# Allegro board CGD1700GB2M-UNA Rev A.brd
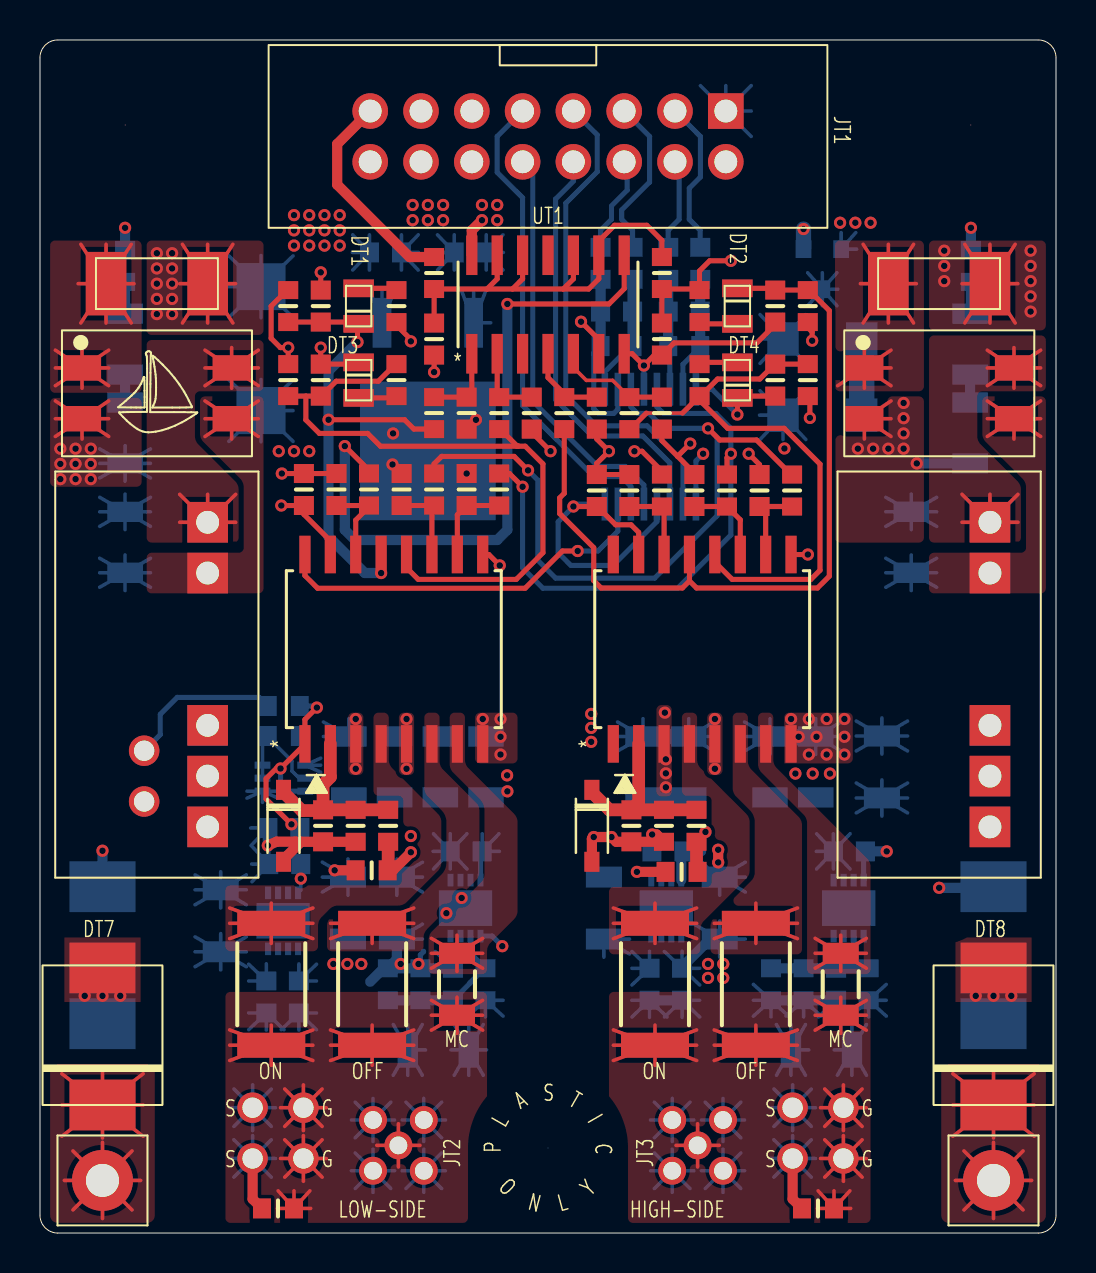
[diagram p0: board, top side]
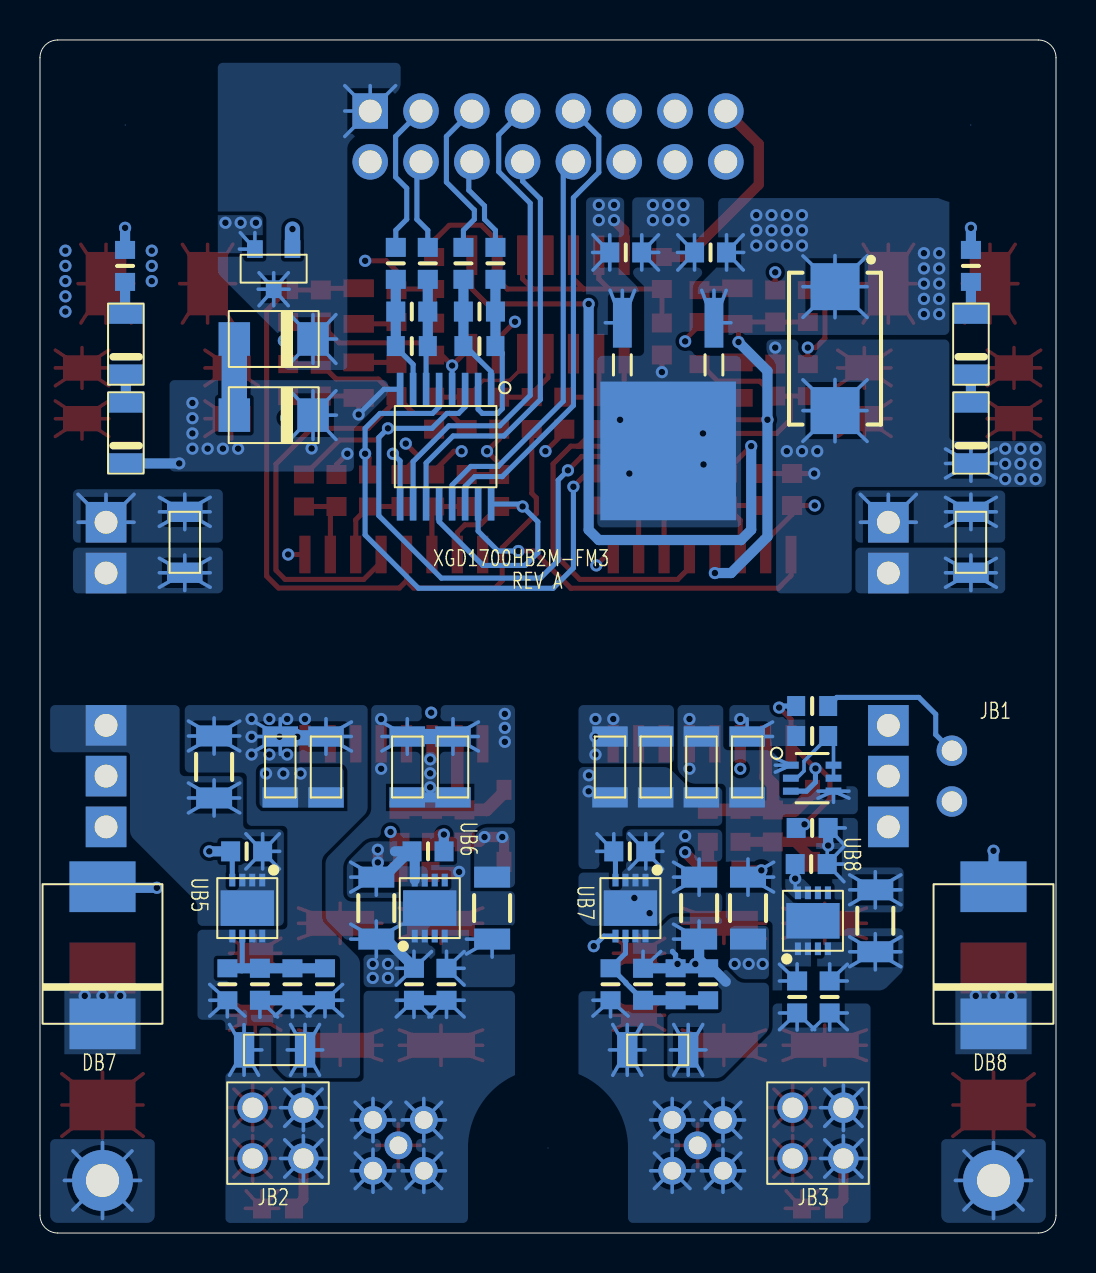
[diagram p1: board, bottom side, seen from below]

Outline 50.8 x 59.69 mm; copper layers: TOP, LAYER2, LAYER3, BOTTOM. Coordinates in mm from the lower left corner of the outline.
Outline path: 0,58.8 0,0.89 arc(0.26,0.26) 0.89,0 49.91,0 arc(50.54,0.26) 50.8,0.89 50.8,58.8 arc(50.54,59.43) 49.91,59.69 0.89,59.69 arc(0.26,59.43) 0,58.8

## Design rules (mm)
constraint set DEFAULT: min track width 0.178
net group FAULT-OUTPUT: nets FAULT-OUTPUT-N FAULT-OUTPUT-P
net group HS-PWM: nets HS-PWM-N HS-PWM-P
net group LS-PWM: nets LS-PWM-N LS-PWM-P
net group RTD-OUTPUT: nets RTD-OUTPUT-N RTD-OUTPUT-P
net group HIGH-SIDE: nets HS-OC N5948959 N6075364
net group LOW-SIDE: nets LS-OC N5949233 N6009832 N6072371 N6084683 RTD-ISO
net group PRIMARY: nets FAULT FLT_HS FLT_LS HS-PWM-INVERTED LS-PWM-INVERTED N5110410 N5786131 N5786223 N5786329 N5786365 N5791884 N5791888 N5813663 N5871306 N5927082 N5941912 N5941952 N6007380 N6007384 N6026363 N6026535 N6032095 N6073188 N6076004 N6088850 N6089152 N6093607 N6093609 PRE-BUFF-RESET RDY_HS RDY_LS RESET RESET INPUT RTD-NON-ISO

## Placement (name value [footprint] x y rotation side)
CB1  2.2uF  [CAPC1608X90N]  21.51 49.06 0 bottom
CB2  2.2uF  [CAPC1608X90N]  17.27 49.06 180 bottom
CB3  56 pF  [CAPC1608X90N]  32.21 46.1 0 bottom
CB4  56 pF  [CAPC1608X90N]  28.83 46.1 0 bottom
CB5  100uF  [CAPMP7343X430N]  11.05 44.25 270 bottom
CB6  10uF  [C_1206]  43.56 34.56 270 bottom
CB7  10uF  [C_1206]  4.25 34.56 270 bottom
CB8  10uF  [C_1206]  38.79 23.32 90 bottom
CB9  10uF  [C_1206]  36.5 23.32 90 bottom
CB10  10uF  [C_1206]  32.44 23.32 270 bottom
CB11  10uF  [C_1206]  30.15 23.32 270 bottom
CB12  10uF  [C_1206]  22.3 23.32 90 bottom
CB13  10uF  [C_1206]  20.02 23.32 90 bottom
CB14  10uF  [C_1206]  17.73 23.32 270 bottom
CB15  10uF  [C_1206]  15.44 23.32 90 bottom
CB16  10000pF  [CAPC1608X90N]  12.19 20.27 180 bottom
CB17  2.2uF  [CAPC1608X90N]  40.47 19.09 180 bottom
CB18  2.2uF  [CAPC1608X90N]  31.4 19.09 0 bottom
CB19  2.2uF  [CAPC1608X90N]  21.31 19.09 180 bottom
CB20  2.2uF  [CAPC1608X90N]  12.24 18.46 0 bottom
CB21  10000pF  [CAPC1608X90N]  39.81 12.45 90 bottom
CB22  2.2uF  [CAPC1608X90N]  32.1 12.45 90 bottom
CB23  10000pF  [CAPC1608X90N]  30.48 12.45 270 bottom
CB24  10000pF  [CAPC1608X90N]  20.65 12.45 270 bottom
CB25  2.2uF  [CAPC1608X90N]  12.94 11.81 90 bottom
CB26  10000pF  [CAPC1608X90N]  11.32 11.81 270 bottom
CB27  10uF  [C_1206]  39.07 9.16 0 bottom
CB28  10uF  [C_1206]  19.91 9.16 0 bottom
CT1  56 pF  [CAPC1608X90N]  14.04 46.38 90 top
CT2  56 pF  [CAPC1608X90N]  36.76 46.38 270 top
CT3  56 pF  [CAPC1608X90N]  19.71 44.73 270 top
CT4  2.2uF  [CAPC1608X90N]  31.09 44.73 270 top
CT5  56 pF  [CAPC1608X90N]  14.04 42.67 90 top
CT6  56 pF  [CAPC1608X90N]  36.76 42.67 270 top
CT7  56 pF  [CAPC1608X90N]  21.33 41.02 270 top
CT8  56 pF  [CAPC1608X90N]  24.59 41.02 270 top
CT9  56 pF  [CAPC1608X90N]  27.84 41.02 270 top
CT10  56 pF  [CAPC1608X90N]  31.09 41.02 270 top
CT11  2.2uF  [CAPC1608X90N]  13.2 37.2 90 top
CT12  56 pF  [CAPC1608X90N]  14.82 37.2 90 top
CT13  56 pF  [CAPC1608X90N]  18.08 37.2 90 top
CT14  56 pF  [CAPC1608X90N]  21.33 37.2 90 top
CT15  2.2uF  [CAPC1608X90N]  27.84 37.15 90 top
CT16  56 pF  [CAPC1608X90N]  29.47 37.15 90 top
CT17  56 pF  [CAPC1608X90N]  32.72 37.15 90 top
CT18  56 pF  [CAPC1608X90N]  35.98 37.15 90 top
CT19  56 pF  [CAPC1608X90N]  14.15 20.37 270 top
CT20  56 pF  [CAPC1608X90N]  29.57 20.37 270 top
DB1  SMAJ5932B-TP  [DO-214AC]  39.12 44.73 180 bottom
DB2  Purple  [D_1206]  46.51 44.47 270 bottom
DB3  Purple  [D_1206]  4.25 44.47 270 bottom
DB4  STPS2150A  [DO-214AC]  39.12 40.92 180 bottom
DB5  Purple  [D_1206]  46.51 40.03 270 bottom
DB6  Purple  [D_1206]  4.25 40.03 270 bottom
DB7  US3M-13  [DO-214AB-SMC]  47.68 10.47 90 bottom
DB8  US3M-13  [DO-214AB-SMC]  3.12 10.47 90 bottom
DT1  LH R974-LP-1  [D_0805]  15.93 46.38 270 top
DT2  LH R974-LP-1  [D_0805]  34.87 46.38 90 top
DT3  LG R971-KN-1  [D_0805]  15.93 42.67 90 top
DT4  LG R971-KN-1  [D_0805]  34.87 42.67 270 top
DT5  BAT42W-TP  [SOD123]  12.18 20.37 270 top
DT6  BAT42W-TP  [SOD123]  27.59 20.37 270 top
DT7  US3M-13  [DO-214AB-SMC]  3.12 6.4 90 top
DT8  US3M-13  [DO-214AB-SMC]  47.68 6.4 90 top
FT1  750 mA  [FUSE_SMD_SSQ2410]  5.84 47.5 180 top
FT2  750 mA  [FUSE_SMD_SSQ2410]  44.96 47.5 180 top
JB1  22-28-1020  [CONN_HEADER_RA_2POS_LOCKING]  5.21 22.86 180 bottom
JB2  SSW-102-01-G-D  [CON_2X2_100MIL_TH]  37.63 6.27 270 bottom
JB3  SSW-102-01-G-D  [CON_2X2_100MIL_TH]  10.63 6.27 270 bottom
JT1  SBH11-PBPC-D08-ST-BK  [CON_2X8_SHROUDED_CORRECTED]  34.29 56.13 270 top
JT2  MMCX-J-P-H-ST-TH1  [MMCX_PLUG_TH]  17.92 4.39 0 top
JT3  MMCX-J-P-H-ST-TH1  [MMCX_PLUG_TH]  32.88 4.39 0 top
JT4  735187-2  [CON_1X1_63MIL]  3.12 2.63 90 top
JT5  735187-2  [CON_1X1_63MIL]  47.68 2.63 90 top
LB1  1 uH  [INDC1608X95N]  33.01 48.51 270 bottom
LB2  1 uH  [INDC1608X95N]  31.41 48.51 270 bottom
LB3  1 uH  [INDC1608X95N]  29.63 48.51 270 bottom
LB4  1 uH  [INDC1608X95N]  28.03 48.51 270 bottom
LT1  10uH  [SRF0905]  5.85 42.01 0 top
LT2  10uH  [SRF0905]  44.96 42.01 0 top
NOREF  -  []  3.68 39.88 0 top
NOREF#2  -  [unnamed#2]  46.55 55.44 0 top
NOREF#3  -  [unnamed#2]  25.4 4.25 0 top
NOREF#4  -  [unnamed#2]  4.25 55.44 0 top
NOREF#5  -  []  25.4 0 90 top
NOREF#6  -  []  0 29.84 0 top
RB1  330  [RESC1608X55N]  46.55 48.39 90 bottom
RB2  330  [RESC1608X55N]  4.25 48.39 90 bottom
RB3  120  [RESC1608X55N]  32.21 44.37 180 bottom
RB4  120  [RESC1608X55N]  28.83 44.37 180 bottom
RB5  2.2k  [RESC1608X55N]  12.19 26.37 180 bottom
RB6  10k  [RESC1608X55N]  12.19 24.87 180 bottom
RB7  0  [RESC3216X70N]  42.09 23.32 90 bottom
RB8  0  [RESC3216X70N]  33.98 16.26 270 bottom
RB9  1.8M  [RESC3216X70N]  28.19 16.26 90 bottom
RB10  0  [RESC3216X70N]  17.84 16.26 270 bottom
RB11  0  [RESC3216X70N]  15.4 16.26 90 bottom
RB12  1.8M  [RESC3216X70N]  9.04 15.62 90 bottom
RB13  2.2k  [RESC1608X55N]  41.43 12.45 90 bottom
RB14  10k  [RESC1608X55N]  38.18 12.45 90 bottom
RB15  10k  [RESC1608X55N]  36.55 12.45 90 bottom
RB16  2.2k  [RESC1608X55N]  22.27 12.45 90 bottom
RB17  10k  [RESC1608X55N]  19.02 12.45 270 bottom
RB18  10k  [RESC1608X55N]  17.39 12.45 270 bottom
RT1  120  [RESC1608X55N]  19.71 48.03 90 top
RT2  10k  [RESC1608X55N]  31.09 48.03 90 top
RT3  10k  [RESC1608X55N]  12.41 46.38 270 top
RT4  330  [RESC1608X55N]  17.82 46.38 270 top
RT5  330  [RESC1608X55N]  32.98 46.38 90 top
RT6  10k  [RESC1608X55N]  38.39 46.38 90 top
RT7  120  [RESC1608X55N]  12.41 42.67 90 top
RT8  330  [RESC1608X55N]  17.82 42.67 90 top
RT9  330  [RESC1608X55N]  32.98 42.67 270 top
RT10  120  [RESC1608X55N]  38.39 42.67 270 top
RT11  120  [RESC1608X55N]  19.71 41.02 90 top
RT12  120  [RESC1608X55N]  22.96 41.02 90 top
RT13  120  [RESC1608X55N]  26.21 41.02 90 top
RT14  120  [RESC1608X55N]  29.47 41.02 90 top
RT15  120  [RESC1608X55N]  16.45 37.2 270 top
RT16  120  [RESC1608X55N]  19.71 37.2 270 top
RT17  120  [RESC1608X55N]  22.96 37.2 270 top
RT18  120  [RESC1608X55N]  31.09 37.15 270 top
RT19  120  [RESC1608X55N]  34.35 37.15 270 top
RT20  120  [RESC1608X55N]  37.6 37.15 270 top
RT21  330  [RESC1608X55N]  15.78 20.37 90 top
RT22  2.2k  [RESC1608X55N]  17.41 20.37 270 top
RT23  330  [RESC1608X55N]  31.2 20.37 90 top
RT24  2.2k  [RESC1608X55N]  32.83 20.37 270 top
RT25  330  [RESC1608X55N]  16.58 18.15 180 top
RT26  330  [RESC1608X55N]  32.08 18.07 180 top
RT27  1  [RESC6432X70N]  11.56 12.45 270 top
RT28  1  [RESC6432X70N]  16.61 12.45 270 top
RT29  0  [RESC3216X70N]  20.85 12.45 270 top
RT30  1  [RESC6432X70N]  30.75 12.45 270 top
RT31  1  [RESC6432X70N]  35.79 12.45 270 top
RT32  0  [RESC3216X70N]  40.04 12.45 270 top
RT33  10k  [RESC1608X55N]  11.9 1.23 180 top
RT34  10k  [RESC1608X55N]  38.9 1.23 180 top
UB1  DMP3056L-7  [SOT_23_3]  41.5 46.36 180 bottom
UB2  MC7805BDTG  [DPAK-3]  19.39 39.13 0 bottom
UB3  2/2  [TSSOP_16]  30.52 39.34 270 bottom
UB4  BC857BS  [SOT363_NEX]  12.19 22.76 180 bottom
UB5  LT3015EDD#TRPBF  [8-WDFN_EXPOSED_PAD]  40.44 16.26 270 bottom
UB6  LT3082EDD#PBF  [8-WDFN_EXPOSED_PAD]  31.31 16.26 90 bottom
UB7  LT3015EDD#TRPBF  [8-WDFN_EXPOSED_PAD]  21.28 16.26 270 bottom
UB8  LT3082EDD#PBF  [8-WDFN_EXPOSED_PAD]  12.15 15.62 90 bottom
UT1  AND_4_2x  [D14]  25.4 46.46 90 top
UT2  UCC21710  [DW16_TEX]  17.69 29.21 90 top
UT3  UCC21710  [DW16_TEX]  33.11 29.21 90 top
UT4  R15P21503D  [MGJ2]  8.38 35.56 270 top
UT5  R15P21503D  [MGJ2]  47.5 35.56 270 top

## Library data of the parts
CB1-CB4 CB6-CB28 CT1-CT20 = CAP
CB5 = CAP_P
DB1 = DIODE_ZENER
DB2 DB3 DB5 DB6 = LED - Purple
DB4 = DIODE_SCHOTTKY_12
DB7 DB8 DT7 DT8 = DIODE_1
DT1-DT4 = LED
DT5 DT6 = DIODE_SCHOTTKY_11
FT1 FT2 = FUSE
JB1 = CON2
JB2 JB3 = CON_2x2_100mil
JT1 = CON16A_Corrected
JT2 JT3 = BNC_5P
JT4 JT5 = HDR_1X1_M
LB1-LB4 = INDUCTOR
LT1 LT2 = CM choke - LPD3015_2
RB1-RB18 RT1-RT34 = RES
UB1 = MOSFET_P_GSD
UB2 = MC7805BDTG: User Part Number: TMP-1562; Tolerance: TOL
UB3 = SN65C1167
UB4 = DUAL_PNP: User Part Number: TMP-1677; Tolerance: TOL
UB5 UB7 = LT3015
UB6 UB8 = LT3082_0
UT1 = AND4_2X: User Part Number: TMP-1541; Tolerance: TOL
UT2 UT3 = UCC21710QDWRQ1: User Part Number: TMP-1688; Tolerance: TOL
UT4 UT5 = MGJ2

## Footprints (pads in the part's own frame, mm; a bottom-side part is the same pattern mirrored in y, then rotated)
8-WDFN_EXPOSED_PAD
  rect 0.635x0.305 smd: 1(-1.4,0.75) 2(-1.4,0.25) 3(-1.4,-0.25) 4(-1.4,-0.75) 5(1.4,-0.75) 6(1.4,-0.25) 7(1.4,0.25) 8(1.4,0.75)
  rect 1.778x2.667 smd: 9(0,0)
C_1206
  rect 1.016x1.778 smd: 1(-1.524,0) 2(1.524,0)
CAPC1608X90N
  rect 0.95x1 smd: 1(-0.8,0) 2(0.8,0)
CAPMP7343X430N
  rect 2.35x2.45 smd: 1(-3.1,0) 2(3.1,0)
CON_1X1_63MIL
  round 3.048 hole 1.651: 1(0,0)
CON_2X2_100MIL_TH
  round 1.524 hole 1.016: 1(0,0) 2(0,-2.54) 3(2.54,0) 4(2.54,-2.54)
CON_2X8_SHROUDED_CORRECTED
  rect 1.778x1.778 hole 1.143: 1(0,0)
  round 1.778 hole 1.143: 2(2.54,0) 3(0,-2.54) 4(2.54,-2.54) 5(0,-5.08) 6(2.54,-5.08) 7(0,-7.62) 8(2.54,-7.62) 9(0,-10.16) 10(2.54,-10.16) 11(0,-12.7) 12(2.54,-12.7) 13(0,-15.24) 14(2.54,-15.24) 15(0,-17.78) 16(2.54,-17.78)
CONN_HEADER_RA_2POS_LOCKING
  round 1.524 hole 1.016: 1(0,1.27) 2(0,-1.27)
D14
  rect 1.981x0.559 smd: 1(-2.464,3.81) 2(-2.464,2.54) 3(-2.464,1.27) 4(-2.464,0) 5(-2.464,-1.27) 6(-2.464,-2.54) 7(-2.464,-3.81) 8(2.464,-3.81) 9(2.464,-2.54) 10(2.464,-1.27) 11(2.464,0) 12(2.464,1.27) 13(2.464,2.54) 14(2.464,3.81)
D_0805
  rect 0.889x1.524 smd: 1(-0.889,0) 2(0.889,0)
D_1206
  rect 1.016x1.778 smd: 1(-1.524,0) 2(1.524,0)
DO-214AB-SMC
  rect 2.54x3.302 smd: A(6.858,0) C(0,0)
DO-214AC
  rect 1.575x1.676 smd: 1(1.968,0) 2(-1.968,0)
DPAK-3
  rect 0.94x2.489 smd: 1(-2.29,-6.413) 3(2.29,-6.413)
  rect 6.782x6.934 smd: 2(0,0)
DW16_TEX
  rect 1.88x0.559 smd: 1(-4.737,4.445) 2(-4.737,3.175) 3(-4.737,1.905) 4(-4.737,0.635) 5(-4.737,-0.635) 6(-4.737,-1.905) 7(-4.737,-3.175) 8(-4.737,-4.445) 9(4.737,-4.445) 10(4.737,-3.175) 11(4.737,-1.905) 12(4.737,-0.635) 13(4.737,0.635) 14(4.737,1.905) 15(4.737,3.175) 16(4.737,4.445)
FUSE_SMD_SSQ2410
  rect 2.032x3.175 smd: 1(-2.54,0) 2(2.54,0)
INDC1608X95N
  rect 0.95x1 smd: 1(-0.8,0) 2(0.8,0)
MGJ2
  rect 2.032x2.032 hole 1.143: 1(0,0) 2(2.54,0) 5(10.16,0) 6(12.7,0) 7(15.24,0)
MMCX_PLUG_TH
  round 1.397 hole 0.889: 1(0,0) 2(-1.27,1.27) 3(1.27,1.27) 4(1.27,-1.27) 5(-1.27,-1.27)
RESC1608X55N
  rect 0.9x1 smd: 1(-0.8,0) 2(0.8,0)
RESC3216X70N
  rect 1.05x1.8 smd: 1(-1.55,0) 2(1.55,0)
RESC6432X70N
  rect 1.25x3.4 smd: 1(-3.05,0) 2(3.05,0)
SOD123
  rect 1x0.75 smd: A(1.8,0) C(-1.8,0)
SOT363_NEX
  rect 0.787x0.356 smd: 1(-1.067,0.65) 2(-1.067,0) 3(-1.067,-0.65) 4(1.067,-0.65) 5(1.067,0) 6(1.067,0.65)
SOT_23_3
  rect 0.787x0.889 smd: 1(3.327,2.87) 2(1.448,2.87) 3(2.388,0.864)
SRF0905
  rect 1.905x1.27 smd: 1(-3.747,1.27) 2(-3.747,-1.27) 3(3.734,-1.27) 4(3.734,1.27)
TSSOP_16
  rect 1.651x0.33 smd: 1(-2.87,2.276) 2(-2.87,1.626) 3(-2.87,0.975) 4(-2.87,0.325) 5(-2.87,-0.325) 6(-2.87,-0.975) 7(-2.87,-1.626) 8(-2.87,-2.276) 9(2.87,-2.276) 10(2.87,-1.626) 11(2.87,-0.975) 12(2.87,-0.325) 13(2.87,0.325) 14(2.87,0.975) 15(2.87,1.626) 16(2.87,2.276)
unnamed#2
  round 0.025 hole 4.445 unplated: (0,0)

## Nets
5V: CB1.2 CT4.1 CT11.1 CT15.1 RT2.1 RT3.1 RT4.2 RT5.2 RT6.1 RT7.2 RT10.2 UB2.3(OUT) UB3.12 UB3.16(VCC) UT1.14 UT2.15 UT3.15
12V: CB2.2 CB5.1 FT1.1 FT2.1 RB1.2 RB2.2 UB1.2(S) UB2.1
+20V_HS: CB18.2 RB8.1 UB6.7 UB6.8 UT5.7
+20V_LS: CB20.2 RB11.1 UB8.7 UB8.8 UT4.7
-5V_HS: CB17.2 RB7.1 UB5.1 UB5.2 UB5.3(SHDN) UB5.9 UT5.5
-5V_LS: CB19.2 RB10.1 UB7.1 UB7.2 UB7.3(SHDN) UB7.9 UT4.5
0: CB1.1 CB2.1 CB5.2 CT1.2 CT2.2 CT3.2 CT4.2 CT5.2 CT6.2 CT7.2 CT8.2 CT9.2 CT10.2 CT11.2 CT12.2 CT13.2 CT14.2 CT15.2 CT16.2 CT17.2 CT18.2 DB4.1(C) DB5.2(CATHODE) DB6.2(CATHODE) DT3.2(C) DT4.2(C) JT1.2 JT1.12 JT1.14 JT1.16 LT1.2 LT2.2 UB1.1 UB2.2 UB3.4 UB3.8 UT1.7 UT2.9 UT3.9
FAULT: UB3.9 UT1.6
FAULT-OUTPUT-N: JT1.8 UB3.11
FAULT-OUTPUT-P: JT1.7 UB3.10
FLT_HS: CT2.1 DT2.2(C) RT6.2 RT13.1 UT3.13
FLT_LS: CT1.1 DT1.2(C) RT3.2 RT11.1 UT2.13
HS-DM: DB7.C(CATHODE) DT8.A
HS-DRAIN: DT8.C(CATHODE) JT5.1
HS-GATE: JB2.2 JB2.4 JT3.1(SIGNAL) RT30.2 RT31.2 RT32.2 RT34.1
HS-OC: CT20.1 DT6.C RT23.2 RT24.1 UT3.2
HS-PWM-INVERTED: RT17.1 RT19.1 UB3.5
HS-PWM-N: JT1.4 LB2.1
HS-PWM-P: JT1.3 LB1.1
HS-SOURCE: CB8.1 CB9.1 CB10.2 CB11.2 CB17.1 CB18.1 CB22.1 CB23.2 CB27.2 CT20.2 DT6.A JB2.1 JB2.3 JT3.2 JT3.3 JT3.4 JT3.5 RB9.2 RB13.1 RT23.1 RT34.2 UB5.4 UB5.5 UT3.3 UT5.6(COM)
HS-VDD: CB10.1 CB11.1 CB22.2 RB8.2 RT26.2 UB6.1 UB6.2 UB6.9 UT3.5
HS-VSS: CB8.2 CB9.2 CB21.1 CB27.1 RB7.2 RB14.1 RB15.1 UB5.7 UB5.8 UT3.8(VEE)
LS-DM: DB8.C(CATHODE) DT7.A
LS-DRAIN: DT7.C(CATHODE) JT4.1
LS-GATE: JB3.2 JB3.4 JT2.1(SIGNAL) RT27.2 RT28.2 RT29.2 RT33.1
LS-OC: CT19.1 DT5.C RT21.2 RT22.1 UT2.2
LS-PWM-INVERTED: RT16.1 RT20.1 UB3.3
LS-PWM-N: JT1.6 LB4.1
LS-PWM-P: JT1.5 LB3.1
LS-SOURCE: CB12.1 CB13.1 CB14.2 CB15.2 CB16.2 CB19.1 CB20.1 CB25.1 CB26.2 CB28.2 CT19.2 DT5.A JB1.2 JB3.1 JB3.3 JT2.2 JT2.3 JT2.4 JT2.5 RB6.1 RB12.2 RB16.1 RT21.1 RT33.2 UB7.4 UB7.5 UT2.3 UT4.6(COM)
LS-VDD: CB14.1 CB15.1 CB25.2 RB11.2 RT25.2 UB4.1 UB4.4(EMITTER) UB8.1 UB8.2 UB8.9 UT2.5
LS-VSS: CB12.2 CB13.2 CB24.1 CB28.1 RB10.2 RB17.1 RB18.1 UB7.7 UB7.8 UT2.8(VEE)
MILLERCLAMP-HS: RT32.1 UT3.7
MILLERCLAMP-LS: RT29.1 UT2.7
NC2: UT1.3
PRE-BUFF-RESET: CT3.1 RT1.1 RT2.2 UT1.9 UT1.10 UT1.12 UT1.13
RDY_HS: CT6.1 RT9.2 RT10.1 RT14.1 UT3.12
RDY_LS: CT5.1 RT7.1 RT8.2 RT12.1 UT2.12
RESET: RT15.1 RT18.1 UT1.8(Y)
RESET INPUT: JT1.15 RT1.2
RTD-ISO: CB16.1 RB5.1 UB4.3 UT2.1
RTD-NON-ISO: UB3.15 UT2.16
RTD-OUTPUT-N: JT1.10 UB3.13
RTD-OUTPUT-P: JT1.9 UB3.14
UNPROTECTED_VIN: DB1.1(C) JT1.1 UB1.3
VOUT_OFF_HS: RT31.1 UT3.6
VOUT_OFF_LS: RT28.1 UT2.6
VOUT_ON_HS: RT30.1 UT3.4
VOUT_ON_LS: RT27.1 UT2.4
N5110410: CT14.1 RT17.2 UT2.10
N5777665: CB6.1 LT2.4 UT5.1
N5777737: CB6.2 LT2.3 UT5.2
N5778706: CB7.1 LT1.4 UT4.1
N5778794: CB7.2 LT1.3 UT4.2
N5780153: FT1.2 LT1.1
N5786131: CB4.1 LB4.2 RB4.2 UB3.2
N5786223: CB4.2 LB3.2 RB4.1 UB3.1
N5786329: CB3.1 LB2.2 RB3.2 UB3.6
N5786365: CB3.2 LB1.2 RB3.1 UB3.7
N5791884: DT1.1 RT4.1
N5791888: DT2.1 RT5.1
N5813663: CT7.1 RT11.2 UT1.1
N5871306: CT9.1 RT13.2 UT1.4
N5927082: DB1.2 DB4.2
N5941912: CT8.1 RT12.2 UT1.2
N5941952: CT10.1 RT14.2 UT1.5
N5948959: CB21.2 RB13.2 RB14.2 RB15.2 UB5.6
N5949233: CB24.2 RB16.2 RB17.2 RB18.2 UB7.6
N6007380: DT3.1 RT8.1
N6007384: DT4.1 RT9.1
N6009832: DB8.A RT22.2 RT25.1
N6026363: CT18.1 RT20.2 UT3.10
N6026535: CT16.1 RT18.2 UT3.14
N6032095: CT12.1 RT15.2 UT2.14
N6067568: CB23.1 RB9.1 UB6.4(SET)
N6067584: CB26.1 RB12.1 UB8.4(SET)
N6072371: JB1.1 RB5.2
N6073188: CT13.1 RT16.2 UT2.11
N6075364: DB7.A RT24.2 RT26.1
N6076004: CT17.1 RT19.2 UT3.11
N6084683: RB6.2 UB4.2 UB4.5 UB4.6
N6088850: DB2.2(CATHODE) DB5.1
N6089152: DB3.2(CATHODE) DB6.1
N6093449: FT2.2 LT2.1
N6093607: DB3.1 RB2.1
N6093609: DB2.1 RB1.1

Pads without a net: JT1 11 13; UB6 3 5 6; UB8 3 5 6; UT1 11; UT3 1 16

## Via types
v1: diameter 0.61, hole 0.33, TOP to BOTTOM, 171 vias

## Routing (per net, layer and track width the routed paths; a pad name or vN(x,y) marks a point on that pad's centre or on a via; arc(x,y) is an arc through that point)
5V: length 47.7
  TOP w0.254: UT3.15 29.93,35.05 29.55,35.43 28.78,35.43 27.87,36.35 CT15.1 v1(26.67,36.35) ; v1(18.54,44.61) 18.54,44.7 17.82,45.42 RT4.2 ; v1(38.61,44.64) 38.61,45.09 38.39,45.3 RT6.1 ; RT3.1 12.36,47.18 11.56,46.37 11.56,44.76 12.02,44.3 v1(12.41,44.3) RT7.2 ; UT2.15 14.52,34.63 13.2,35.95 CT11.1 v1(12.06,36.4) ; v1(38.49,40.78) 38.49,41.77 RT10.2 ; v1(34.54,48.64) 33.48,48.64 32.98,48.14 RT5.2 32.92,47.23 RT2.1 CT4.1
  TOP w0.508: v1(22.1,50.67) 21.59,50.16 UT1.14
  BOTTOM w0.178: UB2.3 21.68,47.17 ; UB2.3 21.07,47.17 ; UB2.3 22.53,45.54 ; UB2.3 22.3,47.17 ; CB1.2 23.15,48.18 ; CB1.2 23.15,49.94 ; CB1.2 23.17,49.06 ; CB1.2 22.31,49.94 ; CB1.2 22.31,48.18
  BOTTOM w0.254: UB3.16 26.79,36.47 v1(26.67,36.35) 25.91,35.59 25.91,34.04 26.54,33.4 28.65,33.4 30.84,35.59 UB3.12
  vias: v1(22.1,51.44) v1(22.86,51.44) v1(22.86,50.67)
12V: length 63.3
  TOP w0.178: FT2.1 47.5,49.47 ; FT2.1 48.76,49.47 ; FT2.1 48.9,47.5 ; FT2.1 46.1,47.5 ; FT2.1 47.5,45.53 ; FT2.1 46.24,45.53 ; FT2.1 46.24,49.47 ; FT2.1 48.76,45.53 ; 6.98,47.5 FT1.1 ; FT1.1 9.78,47.5 ; FT1.1 7.12,45.53 ; FT1.1 8.38,45.53 ; FT1.1 9.64,45.53 ; FT1.1 8.38,49.47 ; FT1.1 9.64,49.47 ; FT1.1 7.12,49.47
  BOTTOM w0.178: CB5.1 12.66,47.35 ; CB5.1 11.05,45.79 ; CB5.1 12.66,45.81 ; CB5.1 11.05,48.9 ; CB5.1 12.66,48.89 ; CB5.1 9.44,45.81 ; CB5.1 9.44,47.35 ; CB5.1 9.44,48.89 ; 15.62,49.06 CB2.2 ; CB2.2 16.47,48.18 ; CB2.2 15.63,49.94 ; CB2.2 15.63,48.18 ; CB2.2 16.47,49.94 ; UB2.1 17.72,47.17 ; UB2.1 16.25,45.54 ; UB2.1 17.1,47.17 ; UB2.1 16.49,47.17 ; UB1.2 40.83,49.23 ; UB1.2 40.06,50.05 ; UB1.2 40.79,50.05
  BOTTOM w0.508: RB2.2 v1(4.25,50.29) ; RB1.2 v1(46.55,50.29)
  vias: v1(5.84,49.02) v1(5.84,48.26) v1(5.84,47.5) v1(5.84,46.74) v1(5.84,45.97) v1(6.6,49.02) v1(6.6,48.26) v1(6.6,47.5) v1(6.6,46.74) v1(6.6,45.97) v1(12.7,50.93) v1(12.7,50.16) v1(12.7,49.4) v1(13.46,50.93) v1(13.46,50.16) v1(13.46,49.4) v1(14.22,50.93) v1(14.22,50.16) v1(14.22,49.4) v1(14.99,50.93) v1(14.99,50.16) v1(14.99,49.4) v1(40,50.55) v1(40.77,50.55) v1(41.53,50.55) v1(45.21,49.15) v1(45.21,48.39) v1(45.21,47.62) v1(49.53,49.15) v1(49.53,48.39) v1(49.53,47.62) v1(49.53,46.86) v1(49.53,46.1)
+20V_HS: length 24.1
  TOP w0.508: v1(33.91,19.18) v1(33.91,18.54)
  LAYER3 w0.178: UT5.7 48.9,21.72 ; UT5.7 48.9,18.92 ; UT5.7 47.5,18.92 ; UT5.7 48.9,20.32 ; UT5.7 46.1,20.32 ; UT5.7 46.1,21.72 ; UT5.7 46.1,18.92
  BOTTOM w0.178: RB8.1 35.27,18.55 ; RB8.1 35.27,17.81 ; RB8.1 33.98,16.9 ; RB8.1 33.98,18.71 ; RB8.1 35.27,17.06
  BOTTOM w0.508: v1(33.91,18.54) 33.91,17.88 RB8.1 33.61,17.81 32.32,19.09 ; 32.32,19.09 CB18.2 32.06,18.96 UB6.8 ; 32.32,19.09 33.06,19.09
+20V_LS: length 9.6
  LAYER3 w0.178: UT4.7 9.78,18.92 ; UT4.7 8.38,18.92 ; UT4.7 6.98,18.92 ; UT4.7 6.98,20.32 ; UT4.7 9.78,20.32
  BOTTOM w0.178: CB20.2 v1(13.04,17.73) 13.04,17.16 UB8.8
  vias: v1(14.67,13.46) v1(15.37,13.46) v1(16.07,13.46)
-5V_HS: length 17.8
  BOTTOM w0.178: 38.83,18.21 CB17.2 ; CB17.2 38.81,19.09 ; CB17.2 40.51,19.98 ; CB17.2 38.83,19.98 ; CB17.2 39.67,18.21 ; CB17.2 40.51,18.21 ; CB17.2 39.67,19.98 ; RB7.1 43.38,21.77 ; RB7.1 43.38,21.02 ; RB7.1 40.81,21.02 ; RB7.1 40.81,22.52 ; RB7.1 42.09,20.86 ; RB7.1 43.38,22.52 ; RB7.1 40.81,21.77 ; RB7.1 42.09,22.67
-5V_LS: length 13.5
  BOTTOM w0.178: 19.65,19.09 CB19.2 ; CB19.2 21.35,19.98 ; CB19.2 20.51,19.98 ; CB19.2 21.35,18.21 ; CB19.2 20.51,18.21 ; CB19.2 19.67,18.21 ; CB19.2 19.67,19.98 ; RB10.1 19.13,17.81 ; RB10.1 17.84,16.9 ; RB10.1 19.13,18.55 ; RB10.1 19.13,17.06 ; RB10.1 17.84,18.71
  vias: v1(18.54,19.86) v1(20.32,16) v1(21.08,16.76)
0: length 140.4
  TOP w0.178: LT1.2 3.44,40.74 ; LT1.2 3.44,39.85 ; LT1.2 0.77,39.85 ; LT1.2 2.1,39.73 ; LT1.2 0.77,41.63 ; LT1.2 3.44,41.63 ; LT1.2 0.77,40.74 ; LT2.2 42.55,41.63 ; LT2.2 42.55,40.74 ; LT2.2 41.22,39.73 ; LT2.2 42.55,39.85
  TOP w0.254: CT18.2 35.98,38.45 v1(35.43,38.99) ; v1(12.09,38) CT11.2 CT12.2 ; CT13.2 v1(17.62,38.45) ; CT16.2 CT15.2 27.84,38.51 v1(28.45,39.12) 27.84,39.72 CT9.2 ; v1(25.53,39.12) 24.59,40.06 CT8.2 ; 31.88,38.86 32.72,38.02 CT17.2 ; 31.88,38.86 31.09,39.64 CT10.2 ; 31.88,38.86 31.88,38.86 v1(32.51,39.5) ; UT3.9 v1(38.39,33.95) ; v1(34.87,40.95) DT4.2 34.96,41.87 CT6.2 ; CT1.2 v1(14.04,48.07) ; DT3.2 15.84,43.47 CT5.2 v1(14.04,44.3) ; CT3.2 v1(19.71,43.07) ; UT2.9 22.44,33.95 v1(22.99,33.4) ; UT1.7 29.6,43.99 v1(30.19,43.4) 30.72,43.93 CT4.2 31.7,44.54 35.84,44.54 36.76,45.46 CT2.2 ; CT7.2 v1(21.8,40.69)
  LAYER2 w0.178: 15.48,54.62 16.51,53.59 ; 16.51,53.59 16.51,54.86 ; 16.51,53.59 16.51,52.32 ; 16.51,53.59 17.54,54.62 ; 16.51,53.59 17.54,52.57 ; 16.51,53.59 15.48,52.57 ; 16.51,53.59 15.24,53.59 ; 34.29,53.59 35.32,52.57 ; 34.29,53.59 33.26,54.62 ; 34.29,53.59 35.32,54.62 ; 34.29,53.59 33.26,52.57 ; 34.29,53.59 35.56,53.59 ; 34.29,53.59 33.02,53.59 ; 34.29,53.59 34.29,54.86 ; 34.29,53.59 34.29,52.32 ; 21.59,53.59 22.62,52.57 ; 21.59,53.59 21.59,54.86 ; 21.59,53.59 20.56,54.62 ; 21.59,53.59 22.62,54.62 ; 21.59,53.59 22.86,53.59 ; 21.59,53.59 20.56,52.57 ; 21.59,53.59 21.59,52.32 ; 19.05,53.59 20.08,54.62 ; 19.05,53.59 18.02,54.62 ; 19.05,53.59 19.05,54.86 ; 19.05,53.59 20.08,52.57 ; 19.05,53.59 19.05,52.32 ; 19.05,53.59 18.02,52.57
  BOTTOM w0.178: 37.15,39.7 DB4.1 ; DB4.1 37.15,42.14 ; DB4.1 36,39.7 ; DB4.1 38.29,39.7 ; DB4.1 36,42.14 ; DB4.1 38.29,42.14 ; DB4.1 35.98,40.92 ; 2.98,39.23 DB6.2 ; DB6.2 5.52,38.5 ; DB6.2 2.98,37.78 ; DB6.2 4.25,39.39 ; DB6.2 5.52,39.23 ; DB6.2 2.98,38.5 ; DB6.2 5.52,37.78 ; DB6.2 4.25,37.61 ; 19.86,49.06 CB1.1 ; CB1.1 19.88,48.18 ; CB1.1 19.88,49.94 ; CB1.1 20.71,49.94 ; CB1.1 20.71,48.18 ; CB5.2 12.66,42.69 ; CB5.2 11.05,42.7 ; CB5.2 9.44,41.15 ; CB5.2 12.66,39.61 ; CB5.2 9.44,39.61 ; CB5.2 9.44,42.69 ; CB5.2 12.66,41.15 ; CB5.2 11.05,39.59 ; CB2.1 18.91,49.94 ; CB2.1 18.93,49.06 ; CB2.1 18.07,48.18 ; CB2.1 18.91,48.18 ; CB2.1 18.07,49.94
  BOTTOM w0.254: v1(34.87,40.95) 33.61,42.21 UB3.8 ; UB3.4 v1(30.19,43.4)
  BOTTOM w0.508: DB5.2 v1(43.84,38.5)
  BOTTOM w0.762: UB1.1 v1(38.18,50.23)
  vias: v1(1.02,39.24) v1(1.02,38.48) v1(1.02,37.72) v1(1.78,39.24) v1(1.78,38.48) v1(1.78,37.72) v1(2.54,39.24) v1(2.54,38.48) v1(2.54,37.72) v1(11.94,39.12) v1(12.7,39.12) v1(13.46,39.12) v1(17.65,40) v1(18.63,51.44) v1(18.63,50.67) v1(19.39,51.44) v1(19.39,50.67) v1(20.15,51.44) v1(20.15,50.67) v1(21.33,38) v1(37.22,39.25) v1(40.89,39.24) v1(41.66,39.24) v1(42.42,39.24) v1(43.18,41.53) v1(43.18,40.77) v1(43.18,40) v1(43.18,39.24)
FAULT: length 14.4
  TOP w0.254: v1(27.05,45.59) 27.94,44.7 UT1.6
  LAYER3 w0.254: v1(33.16,38.99) 33.05,38.89 32.26,38.89 27.05,44.1 v1(27.05,45.59)
  BOTTOM w0.254: UB3.9 32.8,38.63 v1(33.16,38.99)
FAULT-OUTPUT-N: length 21.3
  BOTTOM w0.254: UB3.11 31.49,38.53 30.14,39.88 27.6,39.88 25.78,41.7 25.78,51.73 26.67,52.62 26.67,53.59
FAULT-OUTPUT-P: length 24.7
  BOTTOM w0.254: UB3.10 32.15,38.6 30.35,40.39 27.81,40.39 26.29,41.91 26.29,51.52 27.86,53.1 27.86,54.94 JT1.7
FLT_HS: length 40.5
  TOP w0.254: 32.47,32.63 32.83,32.27 38.87,32.27 39.47,32.86 39.47,46.15 38.44,47.18 RT6.2 CT2.1 36.67,47.27 DT2.2 ; 32.47,32.63 32.12,32.27 28.05,32.27 27.69,32.64 27.69,34.29 25.98,35.99 25.98,36.78 26.21,37.01 RT13.1 ; 32.47,32.63 UT3.13
FLT_LS: length 24.6
  TOP w0.254: v1(15.87,44.58) 15.87,45.43 DT1.2 15.84,45.58 CT1.1 RT3.2 ; UT2.13 v1(17.06,33.02) ; RT11.1 18.7,40.22 18.23,40.69 v1(14.43,40.69)
  BOTTOM w0.508: v1(15.87,44.58) 14.43,43.13 v1(14.43,40.69) 14.43,34.84 16.24,33.02 v1(17.06,33.02)
HS-DM:
  vias: v1(46.79,11.87) v1(47.68,11.87) v1(48.56,11.87)
HS-DRAIN: length 81.5
  TOP w0.178: 47.68,4.75 DT8.C ; DT8.C 49.71,6.4 ; DT8.C 45.64,6.4 ; DT8.C 45.64,7.97 ; DT8.C 49.71,4.84 ; DT8.C 49.71,7.97 ; DT8.C 45.64,4.84 ; DT8.C 47.68,8.06 ; JT5.1 47.68,4.54 ; JT5.1 49.58,2.63 ; JT5.1 49.15,4.11 ; JT5.1 46.2,4.11 ; JT5.1 46.2,1.16 ; JT5.1 47.68,0.73 ; JT5.1 49.15,1.16 ; JT5.1 45.77,2.63
  LAYER2 w0.178: 46.2,4.11 JT5.1 ; JT5.1 45.77,2.63 ; JT5.1 47.68,4.54 ; JT5.1 47.68,0.73 ; JT5.1 49.15,1.16 ; JT5.1 46.2,1.16 ; JT5.1 49.58,2.63 ; JT5.1 49.15,4.11
  LAYER3 w0.178: 46.2,1.16 JT5.1 ; JT5.1 45.77,2.63 ; JT5.1 47.68,4.54 ; JT5.1 49.58,2.63 ; JT5.1 49.15,1.16 ; JT5.1 47.68,0.73 ; JT5.1 49.15,4.11 ; JT5.1 46.2,4.11
  BOTTOM w0.178: JT5.1 47.68,4.54 ; JT5.1 49.58,2.63 ; JT5.1 49.15,4.11 ; JT5.1 49.15,1.16 ; JT5.1 47.68,0.73 ; JT5.1 46.2,4.11 ; JT5.1 46.2,1.16 ; JT5.1 45.77,2.63
HS-GATE: length 69.4
  TOP w0.178: 33.71,9.4 RT31.2 ; RT31.2 33.71,10.16 ; RT31.2 37.87,8.63 ; RT31.2 33.71,8.63 ; RT31.2 35.79,10.4 ; RT31.2 35.79,8.39 ; RT31.2 37.87,9.4 ; RT31.2 37.87,10.16 ; JT3.1 33.96,4.39 ; JT3.1 32.88,5.47 ; JT3.1 31.8,4.39 ; JT3.1 32.88,3.31 ; JB2.2 40.17,7.41 ; JB2.2 39.23,7.21 ; JB2.2 41.31,6.27 ; JB2.2 39.23,5.33 ; JB2.2 40.17,5.13 ; JB2.2 41.11,7.21 ; JB2.2 39.03,6.27 ; JB2.2 41.11,5.33 ; RT30.2 32.83,9.4 ; RT30.2 28.67,8.63 ; RT30.2 28.67,10.16 ; RT30.2 32.83,10.16 ; RT30.2 32.83,8.63 ; RT30.2 28.67,9.4 ; RT30.2 30.75,10.4 ; RT30.2 30.75,8.39 ; RT34.1 39.7,2.11 ; RT34.1 40.49,2.11 ; RT34.1 38.87,1.23 ; RT34.1 38.91,2.11 ; RT34.1 40.53,1.23 ; JB2.4 41.31,3.73 ; JB2.4 40.17,2.59 ; JB2.4 41.11,4.67 ; JB2.4 41.11,2.79 ; JB2.4 39.23,4.67 ; JB2.4 39.03,3.73 ; JB2.4 39.23,2.79 ; JB2.4 40.17,4.87 ; RT32.2 41.32,11.64 ; RT32.2 41.32,10.9 ; RT32.2 40.04,11.8 ; RT32.2 38.75,10.15 ; RT32.2 38.75,10.9 ; RT32.2 38.75,11.64 ; RT32.2 40.04,9.99 ; RT32.2 41.32,10.15
HS-OC: length 9.2
  TOP w0.635: CT20.1 28.47,21.17 27.59,22.05 DT6.C ; CT20.1 RT23.2 RT24.1 ; CT20.1 29.93,21.54 UT3.2
HS-PWM-INVERTED: length 28.9
  TOP w0.254: RT19.1 34.35,38.79 v1(34.54,38.99) ; v1(24.13,37.34) 23.47,38 RT17.1
  BOTTOM w0.254: v1(24.13,37.34) 24.13,33.27 25.15,32.26 31.88,32.26 34.54,34.92 v1(34.54,38.99) 34.54,40.26 33.8,41.01 31.17,41.01 30.84,41.33 UB3.5
HS-PWM-N: length 4.6
  BOTTOM w0.254: 31.75,53.59 31.96,53.39 31.96,50.72 31.41,50.17 LB2.1
HS-PWM-P: length 7.8
  BOTTOM w0.254: LB1.1 33.01,50.17 32.46,50.72 32.46,52.28 33.02,52.83 33.02,54.86 JT1.3
HS-SOURCE: length 210.9
  TOP w0.508: v1(30.61,19.94) 30.83,19.94 RT23.1 CT20.2 28.81,19.57 v1(28.57,19.81) v1(27.69,19.81) 27.59,19.72 DT6.A ; JB2.3 37.63,1.7 RT34.2
  LAYER2 w0.178: 46.1,21.46 UT5.6 ; UT5.6 48.9,24.26 ; UT5.6 46.1,24.26 ; UT5.6 48.9,21.46 ; UT5.6 46.1,22.86 ; UT5.6 48.9,22.86 ; 30.72,2.22 JT3.5 ; JT3.5 30.72,4.01 ; JT3.5 32.69,3.12 ; JT3.5 30.53,3.12 ; JT3.5 31.61,4.2 ; JT3.5 32.5,2.22 ; JT3.5 31.61,2.04 ; JT3.3 35.04,4.76 ; JT3.3 35.04,6.55 ; JT3.3 33.26,6.55 ; JT3.3 34.15,4.58 ; JT3.3 33.07,5.66 ; JT3.3 35.23,5.66 ; JT3.3 34.15,6.74 ; JT3.4 35.23,3.12 ; JT3.4 33.07,3.12 ; JT3.4 35.04,4.01 ; JT3.4 33.26,2.22 ; JT3.4 35.04,2.22 ; JT3.4 34.15,2.04 ; JT3.4 34.15,4.2 ; JT3.2 31.61,6.74 ; JT3.2 32.5,6.55 ; JT3.2 30.72,4.76 ; JT3.2 30.53,5.66 ; JT3.2 32.69,5.66 ; JT3.2 30.72,6.55 ; JT3.2 31.61,4.58 ; 37.63,5.13 JB2.1 ; JB2.1 38.57,7.21 ; JB2.1 37.63,7.41 ; JB2.1 36.69,7.21 ; JB2.1 36.49,6.27 ; JB2.1 38.77,6.27 ; JB2.1 36.69,5.33 ; JB2.1 38.57,5.33 ; 36.69,4.67 JB2.3 ; JB2.3 38.57,2.79 ; JB2.3 37.63,2.59 ; JB2.3 38.77,3.73 ; JB2.3 36.49,3.73 ; JB2.3 36.69,2.79 ; JB2.3 37.63,4.87 ; JB2.3 38.57,4.67
  LAYER3 w0.178: JB2.1 38.57,5.33 ; JB2.1 37.63,7.41 ; JB2.1 36.69,7.21 ; JB2.1 38.77,6.27 ; JB2.1 38.57,7.21 ; JB2.1 37.63,5.13 ; JB2.1 36.49,6.27 ; JB2.1 36.69,5.33 ; 30.72,4.76 JT3.2 ; JT3.2 30.72,6.55 ; JT3.2 32.69,5.66 ; JT3.2 31.61,4.58 ; JT3.2 31.61,6.74 ; JT3.2 30.53,5.66 ; JT3.2 32.5,6.55 ; 36.49,3.73 JB2.3 ; JB2.3 38.57,4.67 ; JB2.3 37.63,4.87 ; JB2.3 38.77,3.73 ; JB2.3 36.69,4.67 ; JB2.3 37.63,2.59 ; JB2.3 38.57,2.79 ; JB2.3 36.69,2.79 ; JT3.3 34.15,6.74 ; JT3.3 34.15,4.58 ; JT3.3 35.04,6.55 ; JT3.3 33.26,6.55 ; JT3.3 33.07,5.66 ; JT3.3 35.04,4.76 ; JT3.3 35.23,5.66 ; JT3.5 31.61,4.2 ; JT3.5 32.5,2.22 ; JT3.5 30.72,2.22 ; JT3.5 30.72,4.01 ; JT3.5 31.61,2.04 ; JT3.5 32.69,3.12 ; JT3.5 30.53,3.12 ; UT5.6 48.9,24.26 ; UT5.6 46.1,24.26 ; UT5.6 46.1,22.86 ; UT5.6 48.9,22.86 ; 33.26,2.22 JT3.4 ; JT3.4 35.04,2.22 ; JT3.4 34.15,4.2 ; JT3.4 34.15,2.04 ; JT3.4 35.04,4.01 ; JT3.4 35.23,3.12 ; JT3.4 33.07,3.12
  BOTTOM w0.178: 34.15,2.04 JT3.4 ; JT3.4 35.23,3.12 ; JT3.4 33.07,3.12 ; JT3.4 35.04,4.01 ; JT3.4 33.26,2.22 ; JT3.4 35.04,2.22 ; JT3.4 34.15,4.2 ; RB13.1 42.31,12.44 ; RB13.1 42.31,10.85 ; RB13.1 40.55,10.85 ; RB13.1 42.31,11.65 ; RB13.1 41.43,10.81 ; 33.07,5.66 JT3.3 ; JT3.3 35.23,5.66 ; JT3.3 34.15,4.58 ; JT3.3 33.26,6.55 ; JT3.3 35.04,4.76 ; JT3.3 35.04,6.55 ; JT3.3 34.15,6.74 ; CB23.2 31.36,10.81 ; CB23.2 29.59,11.65 ; CB23.2 29.59,10.81 ; CB23.2 30.48,10.79 ; 36.69,4.67 JB2.3 ; JB2.3 38.77,3.73 ; JB2.3 38.57,2.79 ; JB2.3 36.69,2.79 ; JB2.3 37.63,2.59 ; JB2.3 38.57,4.67 ; JB2.3 36.49,3.73 ; JB2.3 37.63,4.87 ; 31.22,10.81 CB22.1 ; CB22.1 32.1,10.79 ; CB22.1 32.98,10.81 ; CB22.1 32.98,11.65 ; 37.63,5.13 JB2.1 ; JB2.1 38.77,6.27 ; JB2.1 38.57,5.33 ; JB2.1 36.69,5.33 ; JB2.1 38.57,7.21 ; JB2.1 37.63,7.41 ; JB2.1 36.49,6.27 ; JB2.1 36.69,7.21 ; JT3.5 32.69,3.12 ; JT3.5 32.5,2.22 ; JT3.5 31.61,4.2 ; JT3.5 30.72,2.22 ; JT3.5 30.72,4.01 ; JT3.5 30.53,3.12 ; JT3.5 31.61,2.04 ; JT3.2 32.69,5.66 ; JT3.2 31.61,6.74 ; JT3.2 30.72,4.76 ; JT3.2 30.72,6.55 ; JT3.2 30.53,5.66 ; JT3.2 32.5,6.55 ; JT3.2 31.61,4.58 ; 39.87,7.89 CB27.2 ; CB27.2 41.32,10.43 ; CB27.2 41.32,7.89 ; CB27.2 40.6,10.43 ; CB27.2 40.6,7.89 ; CB27.2 39.71,9.16
  BOTTOM w0.254: UB5.4 41.19,19.01 CB17.1
  BOTTOM w0.508: v1(30.61,19.94) 30.61,19.1 CB18.1 ; CB22.1 CB23.2 ; CB17.1 v1(42.34,19.09) ; CB10.2 CB11.2
  vias: v1(31.24,26.04) v1(31.29,23.7) v1(31.29,23) v1(31.29,22.3) v1(37.77,22.99) v1(38.63,22.99) v1(39.5,22.99)
HS-VDD: length 28.4
  TOP w0.508: RT26.2 v1(29.84,18.07)
  BOTTOM w0.178: RB8.2 33.98,15.61 ; RB8.2 33.98,13.8 ; RB8.2 35.27,15.45 ; RB8.2 35.27,14.71 ; RB8.2 32.7,15.45 ; CB22.2 32.98,13.25 ; CB22.2 31.22,14.08 ; CB22.2 32.98,12.41 ; CB10.1 33.71,24.84 ; CB10.1 33.71,25.57 ; CB10.1 33.71,24.12 ; CB10.1 32.44,25.73 ; CB10.1 32.44,23.95 ; 28.88,24.12 CB11.1 ; CB11.1 30.15,23.95 ; CB11.1 28.88,24.84 ; CB11.1 28.88,25.57 ; CB11.1 30.15,25.73 ; 32.1,13.31 32.1,14.1
  BOTTOM w0.508: RB8.2 33.5,14.71 32.1,13.31 CB22.2
  BOTTOM w0.762: CB10.1 CB11.1
  vias: v1(27.56,25.97) v1(27.56,25.27) v1(27.56,24.57) v1(33.4,13.46) v1(33.4,12.76) v1(33.74,25.72) v1(33.74,23.23) v1(34.16,13.46) v1(34.16,12.76)
HS-VSS: length 48.6
  BOTTOM w0.178: 38.18,10.81 RB14.1 ; RB14.1 37.3,10.85 ; RB14.1 39.06,10.85 ; 40.81,24.87 RB7.2 ; RB7.2 43.38,25.61 ; RB7.2 42.09,23.96 ; RB7.2 40.81,24.12 ; RB7.2 43.38,24.87 ; RB7.2 43.38,24.12 ; RB7.2 40.81,25.61 ; RB7.2 42.09,25.77 ; CB27.1 38.27,7.89 ; CB27.1 37.55,7.89 ; CB27.1 36.82,10.43 ; CB27.1 38.44,9.16 ; CB27.1 36.82,7.89 ; CB27.1 37.55,10.43 ; CB27.1 36.66,9.16 ; CB27.1 38.27,10.43 ; 35.23,25.57 CB9.2 ; CB9.2 36.5,25.73 ; CB9.2 35.23,24.12 ; CB9.2 36.5,23.95 ; CB9.2 35.23,24.84 ; 36.55,10.81 RB15.1 ; RB15.1 35.67,10.85 ; RB15.1 35.67,11.65 ; RB15.1 37.43,10.85 ; RB15.1 35.67,12.44 ; 38.92,10.81 CB21.1 39.81,10.79 ; CB8.2 40.06,24.12 ; CB8.2 40.06,25.57 ; CB8.2 40.06,24.84 ; CB8.2 38.79,23.95 ; CB8.2 38.79,25.73
  BOTTOM w0.508: CB21.1 RB14.1 RB15.1
  BOTTOM w0.762: CB8.2 38.01,24.84 37.94,24.78 37.16,24.78 37.1,24.84 CB9.2
  vias: v1(37.55,25.72) v1(37.93,24.83) v1(38.44,25.72) v1(38.44,23.94) v1(38.82,24.83) v1(39.33,25.72) v1(39.33,23.94) v1(40.22,25.72) v1(40.22,24.83) v1(40.22,23.94)
LS-DM:
  vias: v1(2.24,11.87) v1(3.12,11.87) v1(4.01,11.87)
LS-DRAIN: length 81.5
  TOP w0.178: JT4.1 4.6,4.11 ; JT4.1 3.12,4.54 ; JT4.1 4.6,1.16 ; JT4.1 5.03,2.63 ; JT4.1 1.65,4.11 ; JT4.1 1.22,2.63 ; JT4.1 1.65,1.16 ; JT4.1 3.12,0.73 ; 1.09,4.84 DT7.C ; DT7.C 1.09,6.4 ; DT7.C 3.12,8.06 ; DT7.C 5.16,4.84 ; DT7.C 5.16,7.97 ; DT7.C 3.12,4.75 ; DT7.C 5.16,6.4 ; DT7.C 1.09,7.97
  LAYER2 w0.178: 1.65,4.11 JT4.1 ; JT4.1 5.03,2.63 ; JT4.1 3.12,0.73 ; JT4.1 4.6,1.16 ; JT4.1 4.6,4.11 ; JT4.1 1.65,1.16 ; JT4.1 1.22,2.63 ; JT4.1 3.12,4.54
  LAYER3 w0.178: 1.22,2.63 JT4.1 ; JT4.1 3.12,4.54 ; JT4.1 3.12,0.73 ; JT4.1 4.6,4.11 ; JT4.1 4.6,1.16 ; JT4.1 1.65,4.11 ; JT4.1 1.65,1.16 ; JT4.1 5.03,2.63
  BOTTOM w0.178: 1.22,2.63 JT4.1 ; JT4.1 1.65,4.11 ; JT4.1 1.65,1.16 ; JT4.1 3.12,4.54 ; JT4.1 4.6,1.16 ; JT4.1 3.12,0.73 ; JT4.1 5.03,2.63 ; JT4.1 4.6,4.11
LS-GATE: length 69.4
  TOP w0.178: 9.48,10.16 RT27.2 ; RT27.2 9.48,9.4 ; RT27.2 13.65,8.63 ; RT27.2 11.56,10.4 ; RT27.2 9.48,8.63 ; RT27.2 13.65,10.16 ; RT27.2 13.65,9.4 ; RT27.2 11.56,8.39 ; 19.57,10.15 RT29.2 ; RT29.2 22.13,10.9 ; RT29.2 22.13,10.15 ; RT29.2 19.57,10.9 ; RT29.2 22.13,11.64 ; RT29.2 19.57,11.64 ; RT29.2 20.85,11.8 ; RT29.2 20.85,9.99 ; JB3.2 14.11,5.33 ; JB3.2 12.23,5.33 ; JB3.2 14.31,6.27 ; JB3.2 13.17,7.41 ; JB3.2 13.17,5.13 ; JB3.2 12.03,6.27 ; JB3.2 14.11,7.21 ; JB3.2 12.23,7.21 ; 12.23,4.67 JB3.4 ; JB3.4 13.17,2.59 ; JB3.4 14.11,4.67 ; JB3.4 14.31,3.73 ; JB3.4 14.11,2.79 ; JB3.4 12.03,3.73 ; JB3.4 12.23,2.79 ; JB3.4 13.17,4.87 ; 16.84,4.39 JT2.1 ; JT2.1 19,4.39 ; JT2.1 17.92,5.47 ; JT2.1 17.92,3.31 ; RT28.2 18.69,8.63 ; RT28.2 16.61,10.4 ; RT28.2 14.53,9.4 ; RT28.2 18.69,10.16 ; RT28.2 14.53,10.16 ; RT28.2 18.69,9.4 ; RT28.2 16.61,8.39 ; RT28.2 14.53,8.63 ; 11.91,2.11 RT33.1 ; RT33.1 12.7,2.11 ; RT33.1 13.49,2.11 ; RT33.1 11.87,1.23 ; RT33.1 13.53,1.23
LS-OC: length 9.2
  TOP w0.635: CT19.1 RT21.2 RT22.1 ; CT19.1 14.11,21.13 13.09,21.13 12.18,22.05 DT5.C ; CT19.1 14.15,22.45 14.52,22.81 UT2.2
LS-PWM-INVERTED: length 35.9
  TOP w0.254: RT16.1 19.71,38.48 20.08,38.85 23.71,38.85 v1(24.4,38.16) ; RT20.1 37.55,37.95 35.83,39.67 33.99,39.67 v1(33.4,40.26)
  BOTTOM w0.254: UB3.3 29.54,41.33 29.87,41.01 30.45,41.01 31.2,40.26 v1(33.4,40.26) 33.86,39.8 33.86,35.89 30.73,32.77 25.78,32.77 24.89,33.66 24.89,37.67 v1(24.4,38.16)
LS-PWM-N: length 4.9
  BOTTOM w0.254: 29.21,53.59 29.36,53.45 29.36,52.18 28.57,51.39 28.57,50.72 28.03,50.17 LB4.1
LS-PWM-P: length 8.2
  BOTTOM w0.254: JT1.5 30.48,54.86 30.48,52.58 29.08,51.18 29.08,50.72 29.63,50.17 LB3.1
LS-SOURCE: length 246.2
  TOP w0.508: RT33.2 10.63,1.7 JB3.3 ; DT5.A 12.18,18.7 13.05,19.57 ; 13.05,19.57 12.77,19.57 12.76,19.58 11.83,19.58 v1(11.39,19.39) ; 13.05,19.57 CT19.2 RT21.1
  LAYER2 w0.178: JT2.3 20.08,6.55 ; JT2.3 20.08,4.76 ; JT2.3 19.19,6.74 ; JT2.3 18.11,5.66 ; JT2.3 18.3,6.55 ; JT2.3 20.27,5.66 ; JT2.3 19.19,4.58 ; JT2.4 20.27,3.12 ; JT2.4 19.19,4.2 ; JT2.4 18.11,3.12 ; JT2.4 20.08,4.01 ; JT2.4 20.08,2.22 ; JT2.4 19.19,2.04 ; JT2.4 18.3,2.22 ; 15.57,5.66 JT2.2 ; JT2.2 17.73,5.66 ; JT2.2 15.76,6.55 ; JT2.2 15.76,4.76 ; JT2.2 17.54,6.55 ; JT2.2 16.65,4.58 ; JT2.2 16.65,6.74 ; JT2.5 17.54,2.22 ; JT2.5 15.57,3.12 ; JT2.5 15.76,2.22 ; JT2.5 16.65,2.04 ; JT2.5 17.73,3.12 ; JT2.5 15.76,4.01 ; JT2.5 16.65,4.2 ; JB3.3 11.77,3.73 ; JB3.3 10.63,2.59 ; JB3.3 10.63,4.87 ; JB3.3 9.49,3.73 ; JB3.3 9.69,4.67 ; JB3.3 11.57,4.67 ; JB3.3 9.69,2.79 ; JB3.3 11.57,2.79 ; 4.27,20.65 JB1.2 ; JB1.2 4.06,21.59 ; JB1.2 5.21,20.45 ; JB1.2 6.14,22.53 ; JB1.2 6.35,21.59 ; JB1.2 5.21,22.73 ; JB1.2 6.14,20.65 ; JB1.2 4.27,22.53 ; 9.49,6.27 JB3.1 ; JB3.1 11.77,6.27 ; JB3.1 11.57,7.21 ; JB3.1 9.69,5.33 ; JB3.1 10.63,5.13 ; JB3.1 11.57,5.33 ; JB3.1 10.63,7.41 ; JB3.1 9.69,7.21 ; 6.98,21.46 UT4.6 ; UT4.6 6.98,24.26 ; UT4.6 9.78,21.46 ; UT4.6 9.78,24.26 ; UT4.6 9.78,22.86 ; UT4.6 6.98,22.86
  LAYER3 w0.178: JT2.2 17.54,6.55 ; JT2.2 15.57,5.66 ; JT2.2 16.65,4.58 ; JT2.2 17.73,5.66 ; JT2.2 15.76,6.55 ; JT2.2 15.76,4.76 ; JT2.2 16.65,6.74 ; 10.63,2.59 JB3.3 ; JB3.3 11.57,2.79 ; JB3.3 9.69,2.79 ; JB3.3 9.49,3.73 ; JB3.3 11.57,4.67 ; JB3.3 11.77,3.73 ; JB3.3 9.69,4.67 ; JB3.3 10.63,4.87 ; JB3.1 10.63,7.41 ; JB3.1 11.57,7.21 ; JB3.1 9.69,7.21 ; JB3.1 9.69,5.33 ; JB3.1 11.57,5.33 ; JB3.1 11.77,6.27 ; JB3.1 9.49,6.27 ; JB3.1 10.63,5.13 ; 18.11,3.12 JT2.4 ; JT2.4 20.08,4.01 ; JT2.4 18.3,2.22 ; JT2.4 19.19,2.04 ; JT2.4 19.19,4.2 ; JT2.4 20.27,3.12 ; JT2.4 20.08,2.22 ; 16.65,2.04 JT2.5 ; JT2.5 15.76,2.22 ; JT2.5 15.76,4.01 ; JT2.5 16.65,4.2 ; JT2.5 15.57,3.12 ; JT2.5 17.73,3.12 ; JT2.5 17.54,2.22 ; JB1.2 5.21,22.73 ; JB1.2 6.14,20.65 ; JB1.2 4.27,22.53 ; JB1.2 6.14,22.53 ; JB1.2 5.21,20.45 ; JB1.2 6.35,21.59 ; JB1.2 4.06,21.59 ; JB1.2 4.27,20.65 ; JT2.3 19.19,6.74 ; JT2.3 18.3,6.55 ; JT2.3 20.08,4.76 ; JT2.3 19.19,4.58 ; JT2.3 20.27,5.66 ; JT2.3 18.11,5.66 ; JT2.3 20.08,6.55
  LAYER3 w1.27: UT4.6 6.86,22.86
  BOTTOM w0.178: JB3.1 11.77,6.27 ; JB3.1 11.57,5.33 ; JB3.1 9.69,5.33 ; JB3.1 9.69,7.21 ; JB3.1 11.57,7.21 ; JB3.1 9.49,6.27 ; JB3.1 10.63,7.41 ; JB3.1 10.63,5.13 ; 19.19,2.04 JT2.4 ; JT2.4 18.3,2.22 ; JT2.4 20.08,2.22 ; JT2.4 20.27,3.12 ; JT2.4 20.08,4.01 ; JT2.4 19.19,4.2 ; JT2.4 18.11,3.12 ; JB3.3 11.57,4.67 ; JB3.3 10.63,2.59 ; JB3.3 9.49,3.73 ; JB3.3 11.57,2.79 ; JB3.3 10.63,4.87 ; JB3.3 11.77,3.73 ; JB3.3 9.69,2.79 ; JB3.3 9.69,4.67 ; RB16.1 23.16,10.85 ; RB16.1 21.39,10.85 ; RB16.1 22.27,10.81 ; RB16.1 23.16,11.65 ; 10.6,19.34 CB20.1 ; CB20.1 10.58,18.46 ; CB20.1 10.6,17.58 ; CB20.1 11.44,19.34 ; 7.75,17.17 RB12.2 ; RB12.2 7.75,16.42 ; RB12.2 7.75,17.92 ; RB12.2 10.32,16.42 ; RB12.2 10.32,17.92 ; RB12.2 10.32,17.17 ; RB12.2 9.04,18.08 ; RB12.2 9.04,16.26 ; 20.71,10.43 CB28.2 ; CB28.2 21.44,7.89 ; CB28.2 20.71,7.89 ; CB28.2 22.16,7.89 ; CB28.2 20.55,9.16 ; CB28.2 21.44,10.43 ; CB28.2 22.16,10.43 ; CB28.2 22.33,9.16 ; 19.19,4.58 JT2.3 ; JT2.3 18.11,5.66 ; JT2.3 19.19,6.74 ; JT2.3 20.08,4.76 ; JT2.3 20.08,6.55 ; JT2.3 18.3,6.55 ; JT2.3 20.27,5.66 ; CB19.1 22.11,19.98 ; CB19.1 22.95,19.98 ; CB19.1 22.97,19.09 ; 12.06,10.17 CB25.1 ; CB25.1 13.83,11.01 ; CB25.1 12.94,10.15 ; CB25.1 13.83,10.17 ; 14.17,25.57 CB15.2 ; CB15.2 15.44,25.73 ; CB15.2 14.17,24.84 ; JT2.2 17.73,5.66 ; JT2.2 15.76,6.55 ; JT2.2 15.57,5.66 ; JT2.2 15.76,4.76 ; JT2.2 16.65,6.74 ; JT2.2 16.65,4.58 ; JT2.2 17.54,6.55 ; JT2.5 17.73,3.12 ; JT2.5 16.65,2.04 ; JT2.5 17.54,2.22 ; JT2.5 15.76,2.22 ; JT2.5 15.76,4.01 ; JT2.5 15.57,3.12 ; JT2.5 16.65,4.2 ; 10.43,11.01 CB26.2 ; CB26.2 12.2,10.17 ; CB26.2 10.43,10.17 ; CB26.2 11.32,10.15 ; 10.55,19.39 CB16.2 10.54,20.27
  BOTTOM w0.254: CB19.1 22.03,19.01 UB7.4 ; v1(23.11,14.35) 22.61,14.86 UB7.5
  BOTTOM w0.508: CB16.2 v1(11.39,19.39)
  vias: v1(15.79,25.72) v1(15.79,23.23) v1(23.36,22.9) v1(23.37,22.1)
LS-VDD: length 16.4
  TOP w0.508: RT25.2 v1(14.73,18.15)
  BOTTOM w0.178: CB25.2 12.94,13.47 ; CB25.2 13.83,12.61 ; CB25.2 13.83,13.45 ; 14.12,17.06 RB11.2 ; RB11.2 15.4,18.71 ; RB11.2 14.12,18.55 ; RB11.2 14.12,17.81 ; RB11.2 15.4,16.9 ; UB4.4 11.9,21.76 ; UB4.4 10.35,22.11 ; UB4.4 11.9,22.11 ; UB4.4 10.35,21.76 ; UB4.4 11.13,21.55 ; UB4.1 14.03,23.06 ; UB4.1 14.03,23.76 ; UB4.1 14.03,23.41
  vias: v1(18.33,25.72) v1(18.33,23.23)
LS-VSS: length 22.9
  BOTTOM w0.178: 18.39,7.89 CB28.1 ; CB28.1 19.28,9.16 ; CB28.1 18.39,10.43 ; CB28.1 17.5,9.16 ; CB28.1 17.66,7.89 ; CB28.1 19.12,10.43 ; CB28.1 19.12,7.89 ; CB28.1 17.66,10.43 ; RB10.2 19.13,14.71 ; RB10.2 19.13,15.45 ; RB10.2 17.84,15.61 ; 19.76,14.08 CB24.1 20.65,14.1
  BOTTOM w0.254: RB17.1 19.02,13.92 19.18,14.08 19.18,14.1
  BOTTOM w0.508: RB10.2 17.84,13.7 RB18.1 ; 16.51,12.57 17.18,13.25 RB18.1 ; RB18.1 RB17.1 CB24.1
  vias: v1(18.03,13.46) v1(18.92,13.46) v1(22.14,25.72) v1(23.03,25.72) v1(23.03,24.83) v1(23.03,23.94)
MILLERCLAMP-HS: length 10.3
  TOP w0.178: RT32.1 41.32,14.74 ; RT32.1 38.75,14 ; RT32.1 41.32,13.25 ; RT32.1 41.32,14 ; RT32.1 38.75,14.74 ; RT32.1 40.04,13.09 ; RT32.1 40.04,14.9 ; RT32.1 38.75,13.25
MILLERCLAMP-LS: length 10.3
  TOP w0.178: RT29.1 22.13,13.25 ; RT29.1 19.57,14 ; RT29.1 20.85,13.09 ; RT29.1 22.13,14 ; RT29.1 19.57,14.74 ; RT29.1 20.85,14.9 ; RT29.1 22.13,14.74 ; RT29.1 19.57,13.25
PRE-BUFF-RESET: length 22.4
  TOP w0.254: UT1.10 26.67,47.74 26.16,47.23 ; 22.35,47.23 RT1.1 CT3.1 ; 22.35,47.23 22.86,47.74 UT1.13 ; 22.35,47.23 23.62,47.23 ; 26.16,47.23 23.62,47.23 ; 26.16,47.23 27.43,47.23 27.94,47.74 UT1.9 27.94,49.63 28.73,50.42 30.34,50.42 31.09,49.66 RT2.2 ; 23.62,47.23 24.13,47.74 UT1.12
RDY_HS: length 29.3
  TOP w0.178: 30.32,41.02 32.12,41.02
  TOP w0.254: UT3.12 33.74,33.57 34.61,32.7 38.54,32.7 39,33.16 39,38.47 37.21,40.26 34.39,40.26 33.03,41.62 33.03,41.87 ; 33.03,41.87 33.88,42.73 35.99,42.73 36.74,43.47 CT6.1 RT10.1 ; 33.03,41.87 RT9.2 32.12,41.02 ; RT14.1 29.52,40.22 30.32,41.02
RDY_LS: length 34
  TOP w0.254: 23.86,39.37 23.92,39.37 23.93,39.37 24.26,39.37 25.15,38.48 25.15,34.04 23.81,32.7 18.91,32.7 18.33,33.29 UT2.12 ; 23.86,39.37 23.01,40.22 RT12.1 ; 23.86,39.37 23.85,39.36 17.02,39.36 16.38,40 13.97,40 13.29,40.68 13.29,41.87 ; 13.29,41.87 RT7.1 ; 13.29,41.87 CT5.1 14.06,41.87 14.81,42.62 16.92,42.62 17.77,43.47 RT8.2
RESET: length 45.7
  TOP w0.254: RT15.1 16.45,38.16 v1(15.24,39.37) ; v1(23.37,46.48) 28.45,46.48 29.21,47.24 UT1.8 ; RT18.1 31.09,38.12 30.1,39.11 v1(29.72,39.11)
  LAYER3 w0.254: v1(29.72,39.11) 23.37,45.47 v1(23.37,46.48)
  BOTTOM w0.508: v1(23.37,46.48) 23.37,35.18 22.86,34.67 15.75,34.67 15.24,35.18 v1(15.24,39.37)
RESET INPUT: length 10.7
  TOP w0.508: JT1.15 14.86,54.48 14.86,52.45 18.48,48.83 RT1.2
RTD-ISO: length 11
  TOP w0.254: v1(13.84,26.29) 13.25,25.69 UT2.1 13.25,24.46 v1(12.03,23.24) 11.81,23.24 11.3,22.73 11.3,21.72 v1(12.57,20.45)
  BOTTOM w0.254: v1(12.03,23.24) 12.03,22.56 12.48,22.11 UB4.3 ; CB16.1 12.75,20.27 v1(12.57,20.45) ; v1(13.84,26.29) 13.77,26.37 RB5.1
RTD-NON-ISO: length 19.5
  TOP w0.254: v1(26.88,34.12) 26.12,34.12 24.26,32.26 13.88,32.26 13.25,32.89 UT2.16
  BOTTOM w0.254: v1(26.88,34.12) 27.9,34.12 28.89,35.12 UB3.15
RTD-OUTPUT-N: length 20.4
  BOTTOM w0.254: 24.13,53.59 24.64,53.09 24.64,41.61 27.9,38.35 29.26,38.35 30.19,37.42 UB3.13
RTD-OUTPUT-P: length 23.8
  BOTTOM w0.254: JT1.9 22.86,54.86 22.86,53.07 24.13,51.8 24.13,41.4 27.69,37.85 29.05,37.85 29.54,37.35 UB3.14
UNPROTECTED_VIN: length 25.9
  BOTTOM w0.178: UB1.3 39.85,48.05 ; UB1.3 39.89,47.22 ; UB1.3 38.38,46.39 ; UB1.3 39.12,48.05 ; UB1.3 39.85,46.39 ; UB1.3 38.34,47.22 ; UB1.3 38.38,48.05 ; UB1.3 39.12,46.39 ; DB1.1 38.29,45.95 ; DB1.1 36,45.95 ; DB1.1 37.15,43.51 ; DB1.1 36,43.51 ; DB1.1 37.15,45.95 ; DB1.1 35.98,44.73 ; DB1.1 38.29,43.51 ; JT1.1 34.29,57.4 ; JT1.1 35.56,57.4 ; JT1.1 33.02,57.4 ; JT1.1 35.56,56.13 ; JT1.1 35.56,54.86
VOUT_OFF_HS: length 12.8
  TOP w0.178: 35.79,14.49 RT31.1 ; RT31.1 37.87,16.26 ; RT31.1 33.71,15.5 ; RT31.1 37.87,14.73 ; RT31.1 33.71,14.73 ; RT31.1 35.79,16.5 ; RT31.1 37.87,15.5
VOUT_OFF_LS: length 11.8
  TOP w0.178: RT28.1 18.69,14.73 ; RT28.1 14.53,15.5 ; RT28.1 14.53,14.73 ; RT28.1 16.61,14.49 ; RT28.1 18.69,16.26 ; RT28.1 18.69,15.5
VOUT_ON_HS: length 15
  TOP w0.178: 30.75,14.49 RT30.1 ; RT30.1 30.75,16.5 ; RT30.1 32.83,14.73 ; RT30.1 32.83,15.5 ; RT30.1 28.67,16.26 ; RT30.1 28.67,14.73 ; RT30.1 32.83,16.26 ; RT30.1 28.67,15.5
VOUT_ON_LS: length 15
  TOP w0.178: 11.56,14.49 RT27.1 ; RT27.1 9.48,16.26 ; RT27.1 9.48,14.73 ; RT27.1 13.65,15.5 ; RT27.1 11.56,16.5 ; RT27.1 13.65,14.73 ; RT27.1 9.48,15.5 ; RT27.1 13.65,16.26
N5110410: length 4.3
  TOP w0.254: UT2.10 20.87,35.93 CT14.1 RT17.2
N5777665: length 37.6
  TOP w0.178: LT2.4 50.03,42.39 ; LT2.4 47.36,42.39 ; LT2.4 48.7,44.3 ; LT2.4 50.03,43.28 ; LT2.4 50.03,44.17 ; LT2.4 47.36,43.28 ; LT2.4 47.36,44.17 ; LT2.4 48.7,42.27 ; UT5.1 47.5,36.96 ; UT5.1 46.1,35.56 ; UT5.1 48.9,35.56 ; UT5.1 48.9,36.96 ; UT5.1 46.1,36.96
  BOTTOM w0.178: CB6.1 44.83,35.36 ; CB6.1 42.29,36.81 ; CB6.1 43.56,36.97 ; CB6.1 42.29,35.36 ; CB6.1 42.29,36.08 ; CB6.1 44.83,36.81 ; CB6.1 43.56,35.19 ; CB6.1 44.83,36.08 ; 46.1,36.96 UT5.1 ; UT5.1 46.1,35.56 ; UT5.1 48.9,35.56 ; UT5.1 47.5,36.96 ; UT5.1 48.9,36.96
N5777737: length 20.3
  TOP w0.178: LT2.3 50.03,39.85 ; LT2.3 50.03,41.63 ; LT2.3 48.7,39.73 ; LT2.3 47.36,40.74 ; LT2.3 47.36,41.63 ; LT2.3 47.36,39.85 ; LT2.3 50.03,40.74
  BOTTOM w0.178: 43.56,32.14 CB6.2 ; CB6.2 43.56,33.92 ; CB6.2 44.83,32.31 ; CB6.2 42.29,33.03 ; CB6.2 44.83,33.76 ; CB6.2 42.29,32.31 ; CB6.2 42.29,33.76 ; CB6.2 44.83,33.03
N5778706: length 37.6
  TOP w0.178: UT4.1 9.78,35.56 ; UT4.1 8.38,36.96 ; UT4.1 6.98,36.96 ; UT4.1 6.98,35.56 ; UT4.1 9.78,36.96 ; 8.25,42.39 LT1.4 ; LT1.4 8.25,44.17 ; LT1.4 9.58,44.3 ; LT1.4 10.92,44.17 ; LT1.4 8.25,43.28 ; LT1.4 10.92,43.28 ; LT1.4 10.92,42.39 ; LT1.4 9.58,42.27
  BOTTOM w0.178: 4.25,35.19 CB7.1 ; CB7.1 2.98,36.81 ; CB7.1 2.98,35.36 ; CB7.1 5.52,36.08 ; CB7.1 4.25,36.97 ; CB7.1 2.98,36.08 ; CB7.1 5.52,36.81 ; CB7.1 5.52,35.36 ; UT4.1 8.38,36.96 ; UT4.1 6.98,36.96 ; UT4.1 9.78,36.96 ; UT4.1 9.78,35.56 ; UT4.1 6.98,35.56
N5778794: length 20.3
  TOP w0.178: LT1.3 10.92,41.63 ; LT1.3 10.92,40.74 ; LT1.3 8.25,41.63 ; LT1.3 8.25,40.74 ; LT1.3 10.92,39.85 ; LT1.3 8.25,39.85 ; LT1.3 9.58,39.73
  BOTTOM w0.178: 2.98,33.76 CB7.2 ; CB7.2 5.52,32.31 ; CB7.2 4.25,33.92 ; CB7.2 2.98,33.03 ; CB7.2 4.25,32.14 ; CB7.2 5.52,33.76 ; CB7.2 2.98,32.31 ; CB7.2 5.52,33.03
N5780153: length 27.2
  TOP w0.178: 2.04,49.47 FT1.2 ; FT1.2 4.56,49.47 ; FT1.2 3.3,49.47 ; FT1.2 1.9,47.5 ; FT1.2 2.04,45.53 ; FT1.2 3.3,45.53 ; FT1.2 4.7,47.5 ; FT1.2 4.56,45.53 ; LT1.1 3.44,42.39 ; LT1.1 3.44,44.17 ; LT1.1 0.77,42.39 ; LT1.1 0.77,44.17 ; LT1.1 2.1,44.3 ; LT1.1 3.44,43.28 ; LT1.1 2.1,42.27 ; LT1.1 0.77,43.28
N5786131: length 9
  BOTTOM w0.254: UB3.2 28.89,41.21 28.69,41.01 27.92,41.01 27.69,41.24 27.69,44.03 RB4.2
  BOTTOM w0.508: RB4.2 CB4.1 28.03,46.1 LB4.2
N5786223: length 6.1
  BOTTOM w0.254: UB3.1 28.24,43.09 29.53,44.37 RB4.1
  BOTTOM w0.508: LB3.2 29.63,46.1 CB4.2 RB4.1
N5786329: length 5.5
  BOTTOM w0.254: UB3.6 31.49,44.29 RB3.2
  BOTTOM w0.508: LB2.2 CB3.1 RB3.2
N5786365: length 5.9
  BOTTOM w0.254: RB3.1 33.01,44.32 32.15,43.46 UB3.7
  BOTTOM w0.508: RB3.1 CB3.2 LB1.2
N5791884: length 1.9
  TOP w0.254: DT1.1 17.74,47.27 RT4.1
N5791888: length 1.9
  TOP w0.254: RT5.1 33.06,45.49 DT2.1
N5813663: length 3.9
  TOP w0.254: UT1.1 21.59,42.08 CT7.1 RT11.2
N5871306: length 4.1
  TOP w0.254: UT1.4 25.4,42.8 26.21,41.99 RT13.2 CT9.1
N5927082: length 3.8
  BOTTOM w1.27: DB1.2 DB4.2
N5941912: length 3.8
  TOP w0.254: UT1.2 22.86,41.92 RT12.2 CT8.1
N5941952: length 5.7
  TOP w0.178: RT14.2 28.63,42.66 27.32,42.66 26.67,43.31 UT1.5
  TOP w0.254: CT10.1 RT14.2
N5948959: length 6.5
  BOTTOM w0.254: UB5.6 40.69,13.27 40.71,13.25
  BOTTOM w0.508: RB13.2 CB21.2 RB14.2 RB15.2
N5949233: length 7.5
  BOTTOM w0.254: CB24.2 21.5,12.5 21.5,12.53 22.22,13.25 RB16.2 21.53,13.99 UB7.6
  BOTTOM w0.508: RB18.2 RB17.2 CB24.2
N6007380: length 1.9
  TOP w0.254: RT8.1 17.74,41.78 DT3.1
N6007384: length 1.9
  TOP w0.254: DT4.1 33.06,43.56 RT9.1
N6009832: length 28.3
  TOP w0.508: RT25.1 17.65,18.15 18.54,19.04 v1(18.54,19.05)
  TOP w0.635: RT25.1 17.41,18.17 RT22.2
  LAYER3 w0.508: v1(3.12,19.13) 5.89,19.13 12.45,12.57 16.64,12.57 17.14,13.08 17.14,17.65 v1(18.54,19.05)
  BOTTOM w0.508: DB8.A v1(3.12,19.13)
N6026363: length 4.2
  TOP w0.254: RT20.2 CT18.1 36.28,36.04 UT3.10
N6026535: length 4.1
  TOP w0.254: UT3.14 31.2,36.24 RT18.2 CT16.1
N6032095: length 4.4
  TOP w0.254: UT2.14 15.79,35.67 16.45,36.33 RT15.2 CT12.1
N6067568: length 7.8
  BOTTOM w0.178: RB9.1 29.48,13.96 ; RB9.1 28.19,13.8 ; RB9.1 29.48,14.71 ; 29.59,14.08 CB23.1 ; CB23.1 29.59,12.41 ; CB23.1 30.48,14.1 ; CB23.1 29.59,13.25
N6067584: length 13.3
  BOTTOM w0.178: RB12.1 9.04,14.98 ; RB12.1 10.32,14.82 ; RB12.1 7.75,14.82 ; RB12.1 10.32,13.32 ; RB12.1 9.04,13.17 ; RB12.1 10.32,14.07 ; RB12.1 7.75,14.07 ; RB12.1 7.75,13.32 ; 10.43,12.61 CB26.1 ; CB26.1 10.43,13.45 ; CB26.1 11.32,13.47
N6072371: length 8.1
  BOTTOM w0.254: RB5.2 10.96,26.8 6.86,26.8 6.02,25.95 6.02,24.94 JB1.1
N6073188: length 4.1
  TOP w0.254: UT2.11 19.6,36.29 RT16.2 CT13.1
N6075364: length 19.7
  TOP w0.254: RT24.2 32.83,19.62 v1(33.27,20.07)
  TOP w0.635: RT24.2 32.83,18.12 RT26.1
  LAYER3 w0.508: v1(33.27,20.07) 32.7,19.49 32.7,18.23 33.66,17.27 v1(44.96,17.27)
  BOTTOM w0.508: DB7.A 47.62,17.27 v1(44.96,17.27)
N6076004: length 4.3
  TOP w0.254: UT3.11 35.01,35.68 RT19.2 CT17.1
N6084683: length 5.3
  BOTTOM w0.178: UB4.5 UB4.6 11.13,24.6 RB6.2 11.39,24.82 12.6,23.61 12.6,23.12 12.96,22.76 UB4.2
N6088850: length 1.4
  BOTTOM w0.508: DB2.2 DB5.1
N6089152: length 1.4
  BOTTOM w0.508: DB3.2 DB6.1
N6093449: length 24.3
  TOP w0.178: FT2.2 43.68,45.53 ; FT2.2 42.42,45.53 ; FT2.2 43.68,49.47 ; FT2.2 42.42,49.47 ; FT2.2 43.82,47.5 ; FT2.2 41.16,49.47 ; FT2.2 41.16,45.53 ; FT2.2 41.02,47.5 ; 39.88,42.39 LT2.1 ; LT2.1 42.55,42.39 ; LT2.1 42.55,44.17 ; LT2.1 41.22,42.27 ; LT2.1 42.55,43.28 ; LT2.1 41.22,44.3
N6093607: length 1.6
  BOTTOM w0.508: RB2.1 DB3.1
N6093609: length 1.6
  BOTTOM w0.508: RB1.1 46.55,46.04 DB2.1

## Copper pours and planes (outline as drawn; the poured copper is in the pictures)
5V on BOTTOM: 23.24,51.82 23.42,51.74 23.49,51.56 23.49,44.93 21.19,44.93 21.19,46.38 20.85,46.71 20.85,47.01 20.9,47.25 21.03,47.45 22.1,48.51 22.1,49.81 21.84,49.81 21.66,49.89 21.59,50.07 21.59,51.56 21.66,51.74 21.84,51.82
12V on TOP: 50.04,49.66 50.22,49.58 50.29,49.4 50.29,45.42 50.22,45.24 50.04,45.16 44.7,45.16 44.52,45.24 44.45,45.42 44.45,49.4 44.52,49.58 44.7,49.66
12V on TOP: 5.59,49.66 5.41,49.58 5.33,49.4 5.33,45.19 5.41,45.01 5.59,44.93 10.92,44.93 11.1,45.01 11.18,45.19 11.18,49.4 11.1,49.58 10.92,49.66
12V on BOTTOM: 17.53,44.93 5.59,44.93 5.41,45.01 5.33,45.19 5.33,51.78 16.64,51.78 16.82,51.71 16.89,51.53 16.89,48.64 16.94,48.41 17.07,48.21 17.73,47.55 17.86,47.35 17.91,47.12 17.91,46.86 17.53,46.48
12V on BOTTOM: 39.66,49.02 39.66,50.67 39.74,50.85 39.92,50.93 41.91,50.93 41.91,49.02
12V on LAYER3: 8.25,58.93 8.33,59.11 8.51,59.18 42.29,59.18 42.47,59.11 42.55,58.93 42.55,55.44 43.72,52.61 46.55,51.44 50.04,51.44 50.22,51.36 50.29,51.18 50.29,45.59 39.75,45.59 39.57,45.67 39.5,45.85 39.5,51.95 39.42,52.13 39.24,52.2 35.36,52.2 35.36,53.44 17.65,53.44 17.65,45.59 17.58,45.41 17.4,45.34 0.76,45.34 0.58,45.41 0.51,45.59 0.51,51.18 0.58,51.36 0.76,51.44 4.25,51.44 7.08,52.61 8.25,55.44 ; 7 cut-outs
+20V_HS on BOTTOM: 31.41,19.59 34.13,19.59 34.36,19.55 34.56,19.41 35.28,18.7 35.41,18.5 35.46,18.26 35.46,17.02 35.38,16.84 35.2,16.76 32.82,16.76 32.82,17.34 31.41,17.34
+20V_HS on LAYER3: 48.89,21.84 49.07,21.77 49.15,21.59 49.15,17.96 49.07,17.78 48.89,17.7 33.83,17.7 33.13,18.41 33.13,20.35 34.44,21.66 34.64,21.8 34.88,21.84
+20V_LS on BOTTOM: 14.6,15.37 14.43,15.29 14.35,15.11 14.35,12.95 14.43,12.77 14.6,12.7 15.49,12.7 15.73,12.75 15.93,12.88 16.12,13.07 16.25,13.27 16.3,13.51 16.3,15.11 16.23,15.29 16.05,15.37
